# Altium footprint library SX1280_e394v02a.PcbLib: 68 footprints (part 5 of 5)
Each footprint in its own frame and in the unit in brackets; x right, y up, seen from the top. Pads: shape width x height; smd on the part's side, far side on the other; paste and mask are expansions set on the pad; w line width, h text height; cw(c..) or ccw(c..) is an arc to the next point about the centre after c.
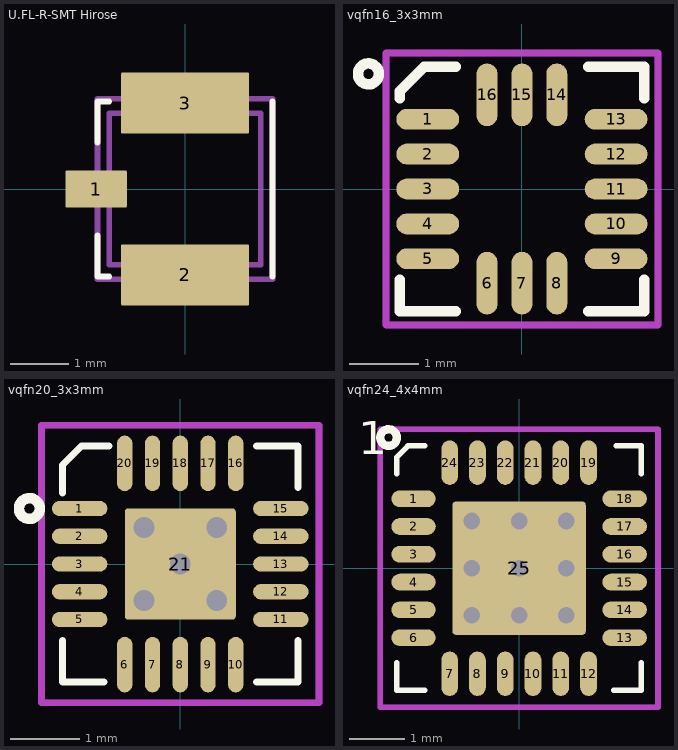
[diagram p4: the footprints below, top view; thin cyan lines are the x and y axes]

## U.FL-R-SMT Hirose [mm] "Hirose U.FL RF receptacle - U.FL-R-SMT"
height 1.2
pads (3):
  rrect5% 1.05x0.635 smd: 1(-1.525,0)
  rrect5% 2.2x1.05 smd: 2(0,-1.475) 3(0,1.475)
Top Overlay:
  lines w0.1: -1.5,-0.8 -1.5,-1.5 -1.3,-1.5 ; -1.5,0.8 -1.5,1.5 -1.3,1.5 ; 1.5,-1.5 1.5,1.5
Mechanical 13:
  lines w0.1: -1.5,-1.55 1.5,-1.55 1.5,1.55 -1.5,1.55 -1.5,-1.55
Mechanical 15:
  lines w0.1: -1.3,-1.3 1.3,-1.3 1.3,1.3 -1.3,1.3 -1.3,-1.3
3D body: height 16, standoff 1.3, extent -1.5,-1.5 1.5,1.5

## vqfn16_3x3mm [mm] "16 Leads, Body 3.0x3.0mm, Pitch 0.50mm, VQFN16"
height 1
pads (16):
  oval 0.9x0.3 smd mask+0.05: 1(-1.35,1) 2(-1.35,0.5) 3(-1.35,0) 4(-1.35,-0.5) 5(-1.35,-1) 9(1.35,-1) 10(1.35,-0.5) 11(1.35,0) 12(1.35,0.5) 13(1.35,1)
  oval 0.3x0.9 smd mask+0.05: 6(-0.5,-1.35) 7(0,-1.35) 8(0.5,-1.35) 14(0.5,1.35) 15(0,1.35) 16(-0.5,1.35)
Top Overlay:
  circle w0.15: c-2.2,1.65 r0.15
  lines w0.15: -1.75,-1.3 -1.75,-1.75 -0.95,-1.75 ; -1.75,1.3 -1.75,1.4 -1.4,1.75 -0.95,1.75 ; 0.95,-1.75 1.75,-1.75 1.75,-1.3 ; 0.95,1.75 1.75,1.75 1.75,1.3
Mechanical 15 keep-out:
  lines w0.1: -1.95,-1.95 1.95,-1.95 1.95,1.95 -1.95,1.95 -1.95,-1.95
3D body: height 1, standoff 0.05, extent -1.5,-1.5 1.5,1.5

## vqfn20_3x3mm [mm] "20 Leads, Body 3.0x3.0mm, Pitch 0.40mm, VQFN20"
height 1
pads (21):
  oval 0.8x0.22 smd mask+0.05: 1(-1.45,0.8) 2(-1.45,0.4) 3(-1.45,0) 4(-1.45,-0.4) 5(-1.45,-0.8) 11(1.45,-0.8) 12(1.45,-0.4) 13(1.45,0) 14(1.45,0.4) 15(1.45,0.8)
  oval 0.22x0.8 smd mask+0.05: 6(-0.8,-1.45) 7(-0.4,-1.45) 8(0,-1.45) 9(0.4,-1.45) 10(0.8,-1.45) 16(0.8,1.45) 17(0.4,1.45) 18(0,1.45) 19(-0.4,1.45) 20(-0.8,1.45)
  rrect5% 1.6x1.6 smd paste-2.2 mask+0.05: 21(0,0)
via 0,0 diameter 0.5 hole 0.3
via -0.525,0.525 diameter 0.5 hole 0.3
via -0.525,-0.525 diameter 0.5 hole 0.3
via 0.525,-0.525 diameter 0.5 hole 0.3
via 0.525,0.525 diameter 0.5 hole 0.3
Top Overlay:
  circle w0.15: c-2.175,0.8 r0.15
  lines w0.1: -1.7,-1.1 -1.7,-1.7 -1.1,-1.7 ; -1.7,1.025 -1.7,1.425 -1.425,1.7 -1.025,1.7 ; 1.1,-1.7 1.7,-1.7 1.7,-1.1 ; 1.1,1.7 1.7,1.7 1.7,1.1
Top Paste:
  region: 0.75,-0.25 0.75,0.25 0.275,0.25 0.275,-0.25
  region: -0.75,0.25 -0.75,-0.25 -0.275,-0.25 -0.275,0.25
  region: -0.25,-0.75 0.25,-0.75 0.25,-0.275 -0.25,-0.275
  region: -0.25,0.75 -0.25,0.275 0.25,0.275 0.25,0.75
Mechanical 15 keep-out:
  lines w0.1: -2,-2 2,-2 2,2 -2,2 -2,-2
3D body: height 1, standoff 0.05, extent -1.5,-1.5 1.5,1.5

## vqfn24_4x4mm [mm] "24 Leads, Body 4.0x4.0mm, Pitch 0.50mm, VQFN24"
height 1
pads (25):
  oval 0.8x0.3 smd mask+0.05: 1(-1.9,1.25) 2(-1.9,0.75) 3(-1.9,0.25) 4(-1.9,-0.25) 5(-1.9,-0.75) 6(-1.9,-1.25) 13(1.9,-1.25) 14(1.9,-0.75) 15(1.9,-0.25) 16(1.9,0.25) 17(1.9,0.75) 18(1.9,1.25)
  oval 0.3x0.8 smd mask+0.05: 7(-1.25,-1.9) 8(-0.75,-1.9) 9(-0.25,-1.9) 10(0.25,-1.9) 11(0.75,-1.9) 12(1.25,-1.9) 19(1.25,1.9) 20(0.75,1.9) 21(0.25,1.9) 22(-0.25,1.9) 23(-0.75,1.9) 24(-1.25,1.9)
  rrect5% 2.4x2.4 smd paste-2.5 mask+0.05: 25(0,0)
via 0.85,-0.85 diameter 0.6 hole 0.3
via 0.85,0.85 diameter 0.6 hole 0.3
via -0.85,0.85 diameter 0.6 hole 0.3
via 0,0 diameter 0.6 hole 0.3
via -0.85,-0.85 diameter 0.6 hole 0.3
via 0,0.85 diameter 0.6 hole 0.3
via -0.85,0 diameter 0.6 hole 0.3
via 0,-0.85 diameter 0.6 hole 0.3
via 0.85,0 diameter 0.6 hole 0.3
Top Overlay:
  circle w0.15: c-2.35,2.35 r0.15
  lines w0.1: -2.2,-1.7 -2.2,-2.2 -1.7,-2.2 ; -2.2,1.7 -2.2,2 -2,2.2 -1.7,2.2 ; 1.7,-2.2 2.2,-2.2 2.2,-1.7 ; 1.75,2.2 2.2,2.2 2.2,1.7
  text "1" at -2.9,2.05 h0.6
Top Paste:
  region: 0.15,-0.85 0.75,-0.85 0.75,-0.2 0.75,-0.1 0.15,-0.1
  region: 0.15,0.1 0.75,0.1 0.75,0.7 0.75,0.85 0.15,0.85
  region: -0.75,0.1 -0.15,0.1 -0.15,0.7 -0.15,0.85 -0.75,0.85
  region: -0.75,-0.85 -0.15,-0.85 -0.15,-0.1 -0.75,-0.1
Mechanical 15 keep-out:
  lines w0.1: -2.5,-2.5 -2.5,2.5 2.5,2.5 2.5,-2.5 -2.5,-2.5
3D body: height 1, standoff 0.05, extent -2,-2 2,2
